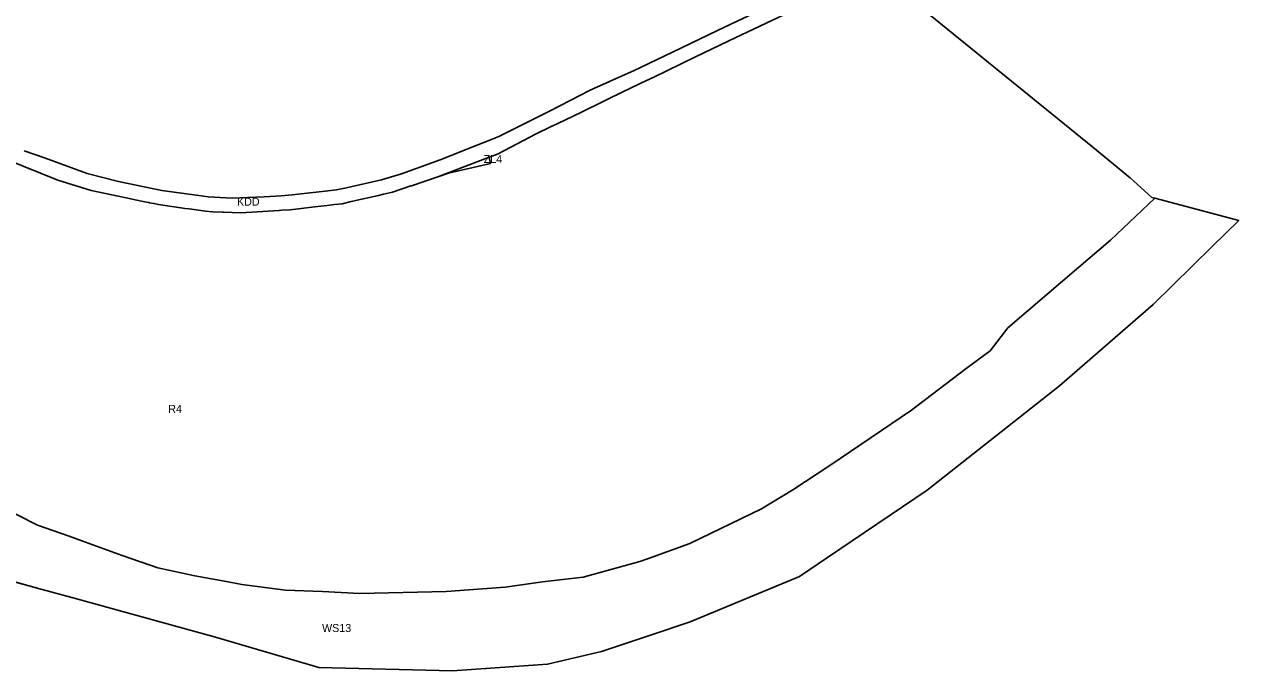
# Model space of a CAD drawing. Extents: x 7428080 to 7432143, y 5545880 to 5549217.
# Drawn here: x 7430738 to 7431580, y 5546185 to 5546633 of the extents above; entities that cross this region are included whole.
import ezdxf

# ---------------------------------------------------------------- set-up
doc = ezdxf.new("R2010")
doc.units = 0
for name, color, linetype in [('CZ_L_granica obszaru objętego planem', 7, 'Continuous'), ('CZ_L_linie rozgraniczające tereny o różnym przeznaczeniu oraz różnych warunkach ich zabudowy i zagospodarowania', 7, 'Continuous'), ('CZ_L_opisy_linie rozgraniczające tereny o różnym przeznaczeniu oraz różnych warunkach ich zabudowy i zagospodarowania', 7, 'Continuous')]:
    doc.layers.add(name, color=color, linetype=linetype)

msp = doc.modelspace()

# ---------------------------------------------------------------- linework, layer by layer
at = {"layer": 'CZ_L_granica obszaru objętego planem'}
for p, q in [((7431366.02, 5546639.74), (7431478.6, 5546548.15)), ((7431478.6, 5546548.15), (7431499.55, 5546531.09)), ((7431499.55, 5546531.09), (7431503.69, 5546527.66)), ((7431503.69, 5546527.66), (7431504.5, 5546526.92)), ((7431504.5, 5546526.92), (7431509.59, 5546522.35)), ((7431509.59, 5546522.35), (7431519.5, 5546513.29)), ((7431519.5, 5546513.29), (7431521.58, 5546512.74)), ((7431521.58, 5546512.74), (7431579.83, 5546497.31)), ((7431579.83, 5546497.31), (7431561.45, 5546479.29)), ((7431561.45, 5546479.29), (7431520.47, 5546439.13)), ((7431520.47, 5546439.13), (7431455.49, 5546382.71)), ((7431455.49, 5546382.71), (7431363.86, 5546310.28)), ((7431363.86, 5546310.28), (7431294.75, 5546263.45)), ((7431294.75, 5546263.45), (7431275.32, 5546250.28)), ((7430750.21, 5546241.35), (7430692.95, 5546257.14)), ((7431275.32, 5546250.28), (7431199.63, 5546218.96)), ((7430770.73, 5546235.69), (7430750.21, 5546241.35)), ((7430870.42, 5546208.2), (7430770.73, 5546235.69)), ((7431199.63, 5546218.96), (7431172.09, 5546209.7)), ((7430942.13, 5546187.14), (7430870.42, 5546208.2)), ((7431172.09, 5546209.7), (7431138.03, 5546198.25)), ((7431138.03, 5546198.25), (7431100.66, 5546189.42)), ((7431034.79, 5546184.95), (7430942.13, 5546187.14)), ((7431100.66, 5546189.42), (7431034.79, 5546184.95))]:
    msp.add_line(p, q, dxfattribs=at)
at = {"layer": 'CZ_L_linie rozgraniczające tereny o różnym przeznaczeniu oraz różnych warunkach ich zabudowy i zagospodarowania'}
for p, q in [((7431292, 5546653.12), (7431226.3, 5546621.87)), ((7431218.59, 5546629.03), (7431257.48, 5546647.63)), ((7431187.37, 5546614.09), (7431218.59, 5546629.03)), ((7431226.28, 5546621.87), (7431202.74, 5546610.6)), ((7431226.3, 5546621.87), (7431226.28, 5546621.87)), ((7431160.32, 5546601.15), (7431187.37, 5546614.09)), ((7431202.74, 5546610.6), (7431174.29, 5546596.84)), ((7431132.82, 5546588.88), (7431154.41, 5546598.52)), ((7431154.41, 5546598.52), (7431160.32, 5546601.15)), ((7431165.74, 5546592.71), (7431155.82, 5546587.91)), ((7431174.29, 5546596.84), (7431165.74, 5546592.71)), ((7431116.31, 5546580.51), (7431129.68, 5546587.48)), ((7431155.27, 5546587.65), (7431124.08, 5546572.56)), ((7431129.68, 5546587.48), (7431132.82, 5546588.88)), ((7431155.82, 5546587.91), (7431155.27, 5546587.65)), ((7431091.41, 5546567.9), (7431102.05, 5546573.16)), ((7431102.05, 5546573.16), (7431116.31, 5546580.51)), ((7431067.25, 5546555.84), (7431091.41, 5546567.9)), ((7431107.78, 5546564.67), (7431102.8, 5546562.27)), ((7431124.08, 5546572.56), (7431107.78, 5546564.67)), ((7431092.74, 5546557.4), (7431065.89, 5546543.4)), ((7431102.8, 5546562.27), (7431092.74, 5546557.4)), ((7431026.17, 5546539.4), (7431050.06, 5546548.93)), ((7431050.06, 5546548.93), (7431062.86, 5546554.07)), ((7431062.86, 5546554.07), (7431067.25, 5546555.84)), ((7430761.02, 5546525.3), (7430725.09, 5546539.78)), ((7430737.68, 5546545.76), (7430751.99, 5546540.68)), ((7430751.99, 5546540.68), (7430781.4, 5546529.96)), ((7430999.42, 5546529.7), (7431026.17, 5546539.4)), ((7431060.15, 5546541.2), (7431024.67, 5546527.6)), ((7431065.89, 5546543.4), (7431060.15, 5546541.2)), ((7431060.15, 5546541.2), (7431060.35, 5546540.19)), ((7431060.35, 5546540.19), (7431060.99, 5546536.8)), ((7431060.99, 5546536.8), (7431032.05, 5546530.09)), ((7430784.23, 5546518.15), (7430761.02, 5546525.3)), ((7430781.4, 5546529.96), (7430803.24, 5546524.38)), ((7430803.24, 5546524.38), (7430833.17, 5546518.13)), ((7430960.14, 5546519.84), (7430985.56, 5546525.48)), ((7430985.56, 5546525.48), (7430999.42, 5546529.7)), ((7431024.67, 5546527.6), (7431006.34, 5546521.41)), ((7431032.05, 5546530.09), (7431024.67, 5546527.6)), ((7430802.94, 5546514.24), (7430784.23, 5546518.15)), ((7430802.92, 5546514.22), (7430802.94, 5546514.24)), ((7430809.63, 5546512.77), (7430802.92, 5546514.22)), ((7430833.17, 5546518.13), (7430858.88, 5546514.58)), ((7430858.88, 5546514.58), (7430865.39, 5546513.7)), ((7430904.25, 5546513.69), (7430915.88, 5546514.39)), ((7430915.88, 5546514.39), (7430923.55, 5546515.1)), ((7430923.55, 5546515.1), (7430944.46, 5546517.44)), ((7430944.46, 5546517.44), (7430954.35, 5546518.59)), ((7430954.35, 5546518.59), (7430960.14, 5546519.84)), ((7430983.45, 5546514.74), (7430966.48, 5546510.86)), ((7430986.96, 5546515.54), (7430983.45, 5546514.74)), ((7430993.11, 5546516.95), (7430986.96, 5546515.54)), ((7431005.91, 5546521.27), (7430993.11, 5546516.95)), ((7431006.34, 5546521.41), (7431005.91, 5546521.27)), ((7431005.91, 5546521.27), (7431005.91, 5546521.27)), ((7430814.73, 5546511.68), (7430809.63, 5546512.77)), ((7430820.41, 5546510.52), (7430814.73, 5546511.68)), ((7430823.75, 5546509.84), (7430820.41, 5546510.52)), ((7430824.27, 5546509.73), (7430823.75, 5546509.84)), ((7430824.66, 5546509.67), (7430824.27, 5546509.73)), ((7430827.66, 5546509.04), (7430824.66, 5546509.67)), ((7430827.86, 5546509), (7430827.66, 5546509.04)), ((7430827.66, 5546509.04), (7430827.66, 5546509.04)), ((7430831.01, 5546508.35), (7430827.86, 5546509)), ((7430846.42, 5546506.1), (7430831.01, 5546508.35)), ((7430846.66, 5546506.07), (7430846.42, 5546506.1)), ((7430848.03, 5546505.87), (7430846.66, 5546506.07)), ((7430849.08, 5546505.72), (7430848.03, 5546505.87)), ((7430849.12, 5546505.71), (7430849.08, 5546505.72)), ((7430852.26, 5546505.3), (7430849.12, 5546505.71)), ((7430865.39, 5546513.7), (7430882, 5546512.85)), ((7430882, 5546512.85), (7430892.52, 5546513.2)), ((7430892.52, 5546513.2), (7430904.25, 5546513.69)), ((7430937.32, 5546506.53), (7430928.02, 5546505.44)), ((7430945.77, 5546507.52), (7430937.32, 5546506.53)), ((7430949.61, 5546507.97), (7430945.77, 5546507.52)), ((7430952.96, 5546508.36), (7430949.61, 5546507.97)), ((7430958.3, 5546508.99), (7430952.96, 5546508.36)), ((7430963.6, 5546510.2), (7430958.3, 5546508.99)), ((7430966.48, 5546510.86), (7430963.6, 5546510.2)), ((7431490.92, 5546483.76), (7431521.58, 5546512.74)), ((7430858.7, 5546504.47), (7430852.26, 5546505.3)), ((7430863.56, 5546503.84), (7430858.7, 5546504.47)), ((7430868.34, 5546503.22), (7430863.56, 5546503.84)), ((7430875.24, 5546503.03), (7430868.34, 5546503.22)), ((7430875.45, 5546503.05), (7430875.24, 5546503.03)), ((7430876.09, 5546503.01), (7430875.45, 5546503.05)), ((7430888.05, 5546502.69), (7430876.09, 5546503.01)), ((7430914.47, 5546504.29), (7430888.05, 5546502.69)), ((7430916.41, 5546504.4), (7430914.47, 5546504.29)), ((7430922.13, 5546504.75), (7430916.41, 5546504.4)), ((7430928.02, 5546505.44), (7430922.13, 5546504.75)), ((7431469.04, 5546464.91), (7431490.92, 5546483.76)), ((7431419.8, 5546422.77), (7431469.04, 5546464.91)), ((7431407.62, 5546406.8), (7431419.8, 5546422.77)), ((7431390.86, 5546394.73), (7431407.62, 5546406.8)), ((7431353.01, 5546365.65), (7431390.86, 5546394.73)), ((7431325.02, 5546346.84), (7431353.01, 5546365.65)), ((7431296.39, 5546327.33), (7431325.02, 5546346.84)), ((7431270.62, 5546310.36), (7431296.39, 5546327.33)), ((7431249.08, 5546297.18), (7431270.62, 5546310.36)), ((7430715.81, 5546301.78), (7430747.03, 5546285.84)), ((7431199.39, 5546273.25), (7431249.08, 5546297.18)), ((7430747.03, 5546285.84), (7430769.01, 5546278.2)), ((7430769.01, 5546278.2), (7430777.87, 5546275.12)), ((7430777.87, 5546275.12), (7430805.7, 5546264.95)), ((7431169.94, 5546262.62), (7431199.39, 5546273.25)), ((7430805.7, 5546264.95), (7430830.57, 5546256.44)), ((7431164.62, 5546260.7), (7431169.94, 5546262.62)), ((7430830.57, 5546256.44), (7430856.17, 5546250.78)), ((7431125.32, 5546249.87), (7431153.85, 5546257.73)), ((7431153.85, 5546257.73), (7431164.62, 5546260.7)), ((7430856.17, 5546250.78), (7430879.21, 5546246.58)), ((7430879.21, 5546246.58), (7430888.65, 5546244.87)), ((7430888.65, 5546244.87), (7430918.94, 5546240.79)), ((7431071.36, 5546242.99), (7431097.04, 5546246.62)), ((7431097.04, 5546246.62), (7431125.32, 5546249.87)), ((7430918.94, 5546240.79), (7430944.69, 5546239.94)), ((7430944.69, 5546239.94), (7430970.59, 5546238.48)), ((7430970.59, 5546238.48), (7431030.26, 5546239.85)), ((7431030.26, 5546239.85), (7431071.36, 5546242.99))]:
    msp.add_line(p, q, dxfattribs=at)
for points in [[(7431343.49, 5546678.46), (7431349.21, 5546667.11), (7431346.72, 5546665.9), (7431351.03, 5546657.57), (7431354.43, 5546651.12), (7431356.66, 5546648.48), (7431366.02, 5546639.74), (7431478.6, 5546548.15), (7431499.55, 5546531.09), (7431503.69, 5546527.66), (7431504.5, 5546526.92), (7431509.59, 5546522.35), (7431519.5, 5546513.29), (7431521.58, 5546512.74)], [(7431521.58, 5546512.74), (7431579.83, 5546497.31), (7431561.45, 5546479.29), (7431520.47, 5546439.13), (7431455.49, 5546382.71), (7431363.86, 5546310.28), (7431294.75, 5546263.45), (7431275.32, 5546250.28), (7431199.63, 5546218.96), (7431172.09, 5546209.7), (7431138.03, 5546198.25), (7431100.66, 5546189.42), (7431034.79, 5546184.95), (7430942.13, 5546187.14), (7430870.42, 5546208.2), (7430770.73, 5546235.69), (7430750.21, 5546241.35), (7430692.95, 5546257.14)]]:
    msp.add_lwpolyline(points, dxfattribs=at)

# ---------------------------------------------------------------- texts
at = {"layer": 'CZ_L_opisy_linie rozgraniczające tereny o różnym przeznaczeniu oraz różnych warunkach ich zabudowy i zagospodarowania'}
for s, p in [('ZL4', (7431056.4, 5546537.21)), ('KDD', (7430885.35, 5546507.59)), ('R4', (7430837.69, 5546363.83)), ('WS13', (7430944.33, 5546211.81))]:
    msp.add_text(s, height=5.549, dxfattribs=at).set_placement(p)

doc.saveas('drawing.dxf')
